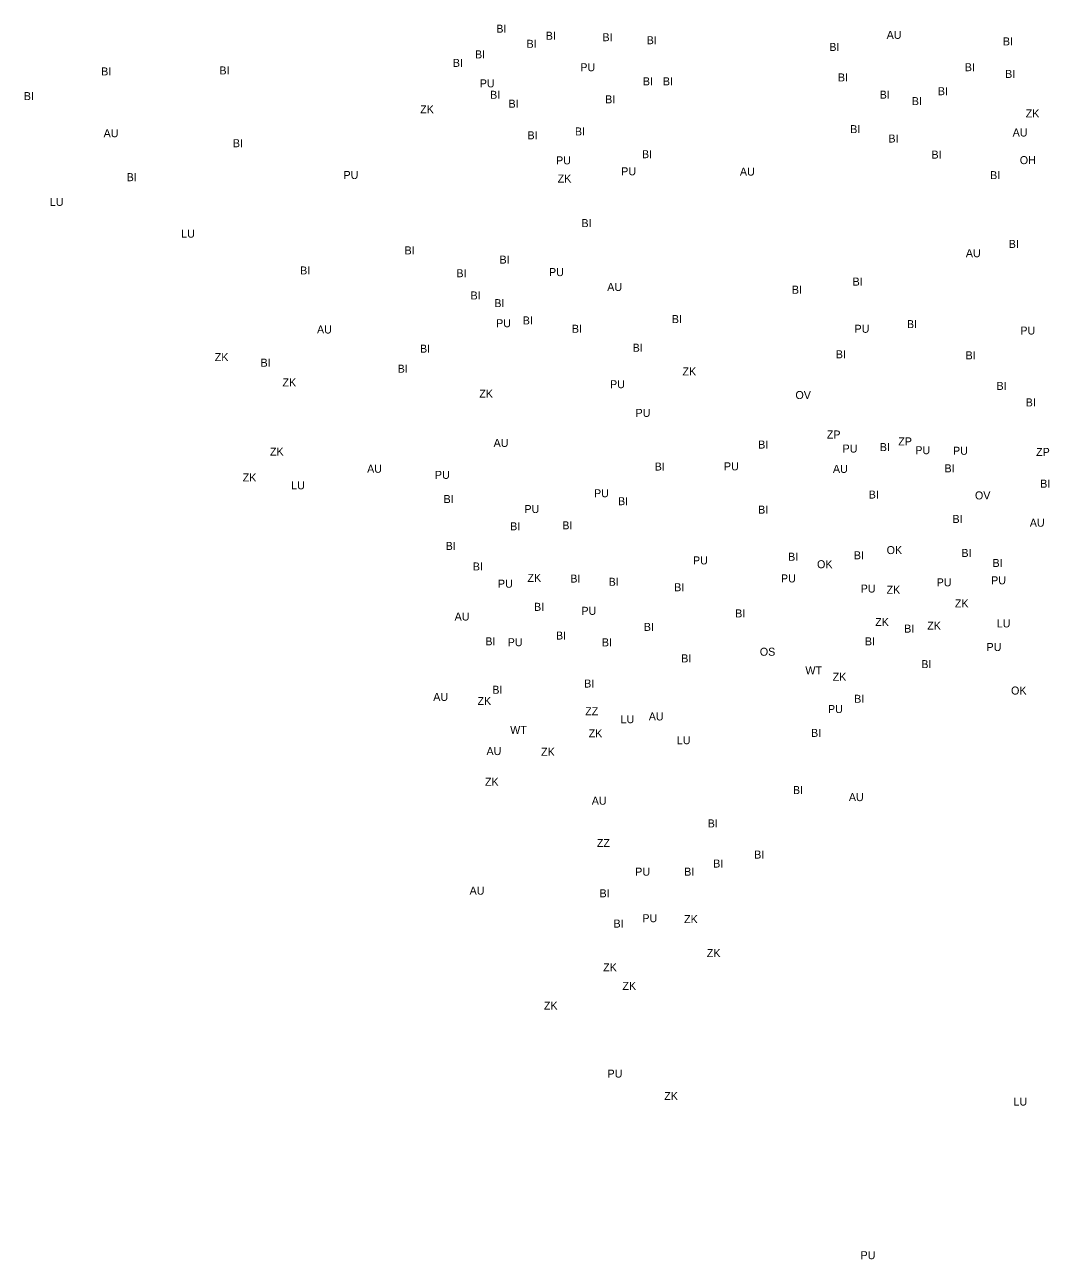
# Model space of a CAD drawing. Extents: x -439151 to -433911, y -1129946 to -1121460.
# Drawn here: x -439151 to -437872, y -1125135 to -1123593 of the extents above; entities that cross this region are included whole.
import ezdxf

# ---------------------------------------------------------------- set-up
doc = ezdxf.new("R2010")
doc.units = 0
doc.layers.add('POPIS PRESTAVBA', color=7, linetype='Continuous')
doc.layers.add('ZASTAVITELNA PLOCHA', color=7, linetype='Continuous')

msp = doc.modelspace()

# ---------------------------------------------------------------- texts
at = {"layer": 'POPIS PRESTAVBA'}
for s, p in [('BI', (-438562.4, -1123602.7)), ('BI', (-438524.6, -1123621.6)), ('BI', (-438429.9, -1123613.3)), ('BI', (-438374.6, -1123617.1)), ('AU', (-438074.9, -1123610.4)), ('BI', (-438589, -1123634.8)), ('BI', (-438146.5, -1123625.5)), ('BI', (-438908.3, -1123654.9)), ('PU', (-438457.5, -1123650.9)), ('BI', (-437977.3, -1123650.8)), ('BI', (-439056, -1123656.1)), ('BI', (-437926.9, -1123659.2)), ('PU', (-438583.1, -1123671)), ('BI', (-439152.6, -1123686.9)), ('BI', (-438547.2, -1123696.4)), ('BI', (-438426.5, -1123691)), ('BI', (-438043.5, -1123693.2)), ('ZK', (-438657.5, -1123703.4)), ('ZK', (-437901.2, -1123708.6)), ('BI', (-438120.4, -1123728.2)), ('AU', (-437917.5, -1123732.4)), ('AU', (-439052.9, -1123733.3)), ('BI', (-438891.4, -1123745.8)), ('BI', (-438072.7, -1123739.9)), ('BI', (-438380.5, -1123759.5)), ('PU', (-438487.8, -1123767.2)), ('BI', (-439024.1, -1123788.2)), ('PU', (-438753.3, -1123785.5)), ('ZK', (-438485.8, -1123789.9)), ('PU', (-438406.4, -1123780.9)), ('AU', (-438258.2, -1123781.3)), ('BI', (-437945.7, -1123785.7)), ('LU', (-439120, -1123819.1)), ('BI', (-438456.1, -1123845.6)), ('LU', (-438956, -1123858.8)), ('BI', (-438677, -1123879.7)), ('AU', (-437976, -1123883.2)), ('BI', (-438807.5, -1123904.8)), ('PU', (-438496.6, -1123906.8)), ('AU', (-438423.9, -1123925.4)), ('BI', (-438117.4, -1123918.7)), ('BI', (-438594.6, -1123936)), ('AU', (-438786.4, -1123978.5)), ('PU', (-438562.7, -1123970.7)), ('BI', (-438343.2, -1123965.5)), ('PU', (-438115, -1123977.6)), ('BI', (-438049.5, -1123971.8)), ('BI', (-438657.7, -1124002.5)), ('BI', (-438392.1, -1124001.3)), ('BI', (-438138.4, -1124009.5)), ('ZK', (-438914.1, -1124013)), ('BI', (-438856.9, -1124020)), ('ZK', (-438329.9, -1124030.9)), ('ZK', (-438829.5, -1124044.6)), ('PU', (-438420.4, -1124046.9)), ('ZK', (-438583.7, -1124058.7)), ('OV', (-438188.8, -1124060.4)), ('BI', (-437901.2, -1124069.6)), ('PU', (-438388.5, -1124082.7)), ('ZP', (-438149.6, -1124109.7)), ('ZK', (-438845.1, -1124131.1)), ('AU', (-438565.8, -1124120.2)), ('BI', (-438235.3, -1124122.3)), ('PU', (-438129.9, -1124127.3)), ('ZP', (-438060.4, -1124118.3)), ('PU', (-438039.1, -1124129.3)), ('PU', (-437992, -1124130)), ('ZP', (-437888.2, -1124131.5)), ('ZK', (-438879.2, -1124163.4)), ('AU', (-438723.8, -1124152.5)), ('PU', (-438639.1, -1124160.1)), ('BI', (-438364.6, -1124149.7)), ('PU', (-438278.1, -1124149.5)), ('AU', (-438142, -1124152.7)), ('BI', (-438002.7, -1124152)), ('LU', (-438818.6, -1124173.2)), ('BI', (-438628.3, -1124190.3)), ('BI', (-438097.3, -1124184.7)), ('OV', (-437964.6, -1124185.8)), ('BI', (-438480, -1124223.2)), ('BI', (-437992.7, -1124215.2)), ('AU', (-437896.1, -1124219.9)), ('OK', (-438074.9, -1124254.1)), ('PU', (-438316.8, -1124267)), ('BI', (-438198, -1124262.4)), ('OK', (-438161.8, -1124271.8)), ('BI', (-438115.8, -1124260.6)), ('BI', (-437942.7, -1124270.2)), ('BI', (-438591.8, -1124274.6)), ('PU', (-438560.4, -1124296.1)), ('ZK', (-438523.5, -1124288.8)), ('BI', (-438340.2, -1124300.5)), ('PU', (-438206.9, -1124289.5)), ('PU', (-438107.3, -1124302.2)), ('PU', (-438012.4, -1124294.4)), ('PU', (-437944.4, -1124291.9)), ('ZK', (-438075, -1124303.7)), ('BI', (-438515.3, -1124325)), ('BI', (-438264.1, -1124333.2)), ('ZK', (-437989.7, -1124320.8)), ('AU', (-438614.5, -1124337.1)), ('ZK', (-438089.2, -1124344)), ('ZK', (-438024.2, -1124348.5)), ('LU', (-437937.4, -1124345.7)), ('BI', (-438378.2, -1124350)), ('PU', (-438548.2, -1124369.2)), ('BI', (-438430.6, -1124369.4)), ('BI', (-438102, -1124368.1)), ('PU', (-437950.1, -1124375.2)), ('OS', (-438233.3, -1124381.1)), ('WT', (-438176.4, -1124404.5)), ('BI', (-438031.6, -1124396.6)), ('BI', (-438452.7, -1124420.8)), ('ZK', (-438142.3, -1124412.4)), ('AU', (-438641.2, -1124437.5)), ('BI', (-438567.4, -1124428.6)), ('BI', (-438115.5, -1124439.9)), ('OK', (-437919.5, -1124429.6)), ('ZK', (-438585.9, -1124442.6)), ('ZZ', (-438451.4, -1124455.4)), ('PU', (-438148.2, -1124452.7)), ('LU', (-438407.2, -1124465.4)), ('AU', (-438372, -1124461.9)), ('WT', (-438545.1, -1124478.7)), ('ZK', (-438447.1, -1124483.1)), ('BI', (-438169.3, -1124482.5)), ('LU', (-438336.9, -1124491.6)), ('AU', (-438574.7, -1124505.2)), ('ZK', (-438506.5, -1124506.1)), ('ZK', (-438576.6, -1124543.6)), ('AU', (-438122.1, -1124562.7)), ('AU', (-438443.2, -1124567.2)), ('BI', (-438298.4, -1124595.6)), ('ZZ', (-438436.8, -1124620)), ('BI', (-438240.3, -1124634.5)), ('PU', (-438388.9, -1124655.9)), ('BI', (-438291.5, -1124645.7)), ('AU', (-438595.8, -1124679.6)), ('PU', (-438380, -1124714)), ('ZK', (-438327.9, -1124715.2)), ('BI', (-438416, -1124720.7)), ('ZK', (-438299.5, -1124757.6)), ('ZK', (-438429, -1124775.4)), ('ZK', (-438404.9, -1124798.6)), ('ZK', (-438503, -1124823.3)), ('PU', (-438423.5, -1124908.2)), ('ZK', (-438352.7, -1124936.1)), ('LU', (-437916.5, -1124943.1)), ('PU', (-438107.5, -1125135))]:
    msp.add_text(s, height=10, dxfattribs=at).set_placement(p)
at = {"layer": 'ZASTAVITELNA PLOCHA'}
for s, p in [('BI', (-438500.7, -1123611.5)), ('BI', (-437929.7, -1123618.6)), ('BI', (-438616.7, -1123645.4)), ('BI', (-438379.4, -1123668.5)), ('BI', (-438354.4, -1123668.5)), ('BI', (-438135.8, -1123663.6)), ('BI', (-438570.2, -1123685.3)), ('BI', (-438083.6, -1123685.1)), ('BI', (-438010.9, -1123680.8)), ('BI', (-438464.2, -1123731.1)), ('BI', (-438523.5, -1123735.9)), ('BI', (-438018.9, -1123760)), ('OH', (-437908.6, -1123766.9)), ('BI', (-437922.4, -1123871.6)), ('BI', (-438558.4, -1123891.2)), ('BI', (-438612.3, -1123908.2)), ('BI', (-438193.3, -1123928.8)), ('BI', (-438564.9, -1123945.6)), ('BI', (-438529.4, -1123967.2)), ('BI', (-438468, -1123977.6)), ('PU', (-437907.9, -1123979.8)), ('BI', (-437976.3, -1124010.8)), ('BI', (-438685.6, -1124027.5)), ('BI', (-437937.7, -1124049)), ('BI', (-438083.5, -1124125.4)), ('BI', (-437883.1, -1124171.1)), ('PU', (-438440.4, -1124183.1)), ('BI', (-438410.4, -1124193)), ('PU', (-438527.3, -1124202.8)), ('BI', (-438235.4, -1124203.6)), ('BI', (-438545.2, -1124224.4)), ('BI', (-438625.7, -1124248.9)), ('BI', (-437981.5, -1124257.7)), ('BI', (-438470, -1124289.7)), ('BI', (-438422.1, -1124293.7)), ('PU', (-438456.1, -1124330)), ('BI', (-438487.9, -1124360.9)), ('BI', (-438053, -1124352.2)), ('BI', (-438576.1, -1124368.1)), ('BI', (-438331.4, -1124389.4)), ('BI', (-438191.9, -1124553.9)), ('BI', (-438327.8, -1124655.9)), ('BI', (-438433.5, -1124682.9))]:
    msp.add_text(s, height=10, dxfattribs=at).set_placement(p)

doc.saveas('drawing.dxf')
